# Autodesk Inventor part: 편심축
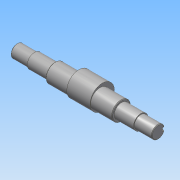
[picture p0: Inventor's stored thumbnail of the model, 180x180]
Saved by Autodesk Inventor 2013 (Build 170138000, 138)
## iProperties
Created: 2015-10
Part Number: 편심축
Document SubType Name: Modeling
Designer: mdu
Density: 7.86 g/cm^3
Material: 강철, 연강
Mass: 1327.93 g
Surface Area: 248.524 cm^2
Volume: 168.947 cm^3
Author: mdu
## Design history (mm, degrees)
sketch "스케치1"
  geometry: L1 (-20.5, -41.331)-(-20.5, 32.669) reference; L2 (7.5, -30.031)-(7.5, 21.369) reference; L3 (135.5, -30.331)-(135.5, 21.669) reference; L4 (121.5, 21.369)-(121.5, -30.031) reference; L5 (184.5, -4.331)-(-57.5, -4.331); L6 (184.5, -4.331)-(184.5, 6.669); L7 (154.5, 8.169)-(121.5, 8.169); L8 (121.5, 8.169)-(121.5, 11.669); L9 (121.5, 11.669)-(7.5, 11.669); L10 (7.5, 11.669)-(7.5, 8.169); L11 (7.5, 8.169)-(-27.5, 8.169); L12 (-27.5, 8.169)-(-27.5, 6.669); L13 (-27.5, 6.669)-(-57.5, 6.669); L14 (-57.5, 6.669)-(-57.5, -4.331); L15 (154.5, 8.169)-(154.5, 6.669); L16 (154.5, 6.669)-(184.5, 6.669); C1 r 32.5 at (64.5, -4.331) reference; 1 further point
  constraints: 24 end point, 8 perpendicular, 5 point on line, 3 parallel, 2 collinear
  dimensions: "d1" = 25 diameter of L11 L5; "d2" = 32 diameter of L9 L5; "d3" = 22 diameter of L13 L5; "d4" = 35 distance of L10.end L11.end; "d5" = 30 distance of L12.end L13.end; "d15" = 33 distance of L7.start L7.end; "d26" = 30 distance of L15.end L6.end
revolve "회전1" sketch "스케치1" stored, may be unused: angle "d6" = 90 deg
node "작업 평면1"
sketch "스케치2"
  geometry: C1 r 16 at (0, 0) reference; C2 r 16 at (0, 0) reference; C3 r 20.75 at (0, 4); C4 r 16 at (0, 0) reference; 1 further point
  constraints: 1 centre point, 1 vertical alignment
  dimensions: "d8" = 41.5 diameter of C3; "d25" = 4 distance of C3.centre C1.centre
extrude "돌출1" join sketch "스케치2" stored distance "d9" = 40; taper "d10" = 0 deg
chamfer "모따기1" distance "d11" = 1; stored, may be unused: second distance "d12" = 2, angle "d13" = 45 deg
node "작업 평면2"
sketch "스케치3"
  geometry: L1 (-15, -10)-(-15, 10) reference; L2 (-15, 3)-(0, 3); L3 (0, -3)-(-15, -3); A1 r 3 centre (0, 0) between (0, -3) and (0, 3); 2 further points
  constraints: 4 end point, 2 perpendicular, 2 point on circle, 2 point on line, 2 tangent, 1 centre point, 1 horizontal alignment, 1 midpoint
  dimensions: "d16" = 18 dimension on A1 L1; "d17" = 6 distance between parallel lines of L3 L2
extrude "돌출2" cut sketch "스케치3" distance "d18" = 3.5; taper "d19" = 0 deg
node "작업 평면3"
node "솔리드1"
mirror "대칭1"
node "참조1"
node "참조2"
node "참조3"
node "참조4"
node "참조5"
node "투영된 루프1"
